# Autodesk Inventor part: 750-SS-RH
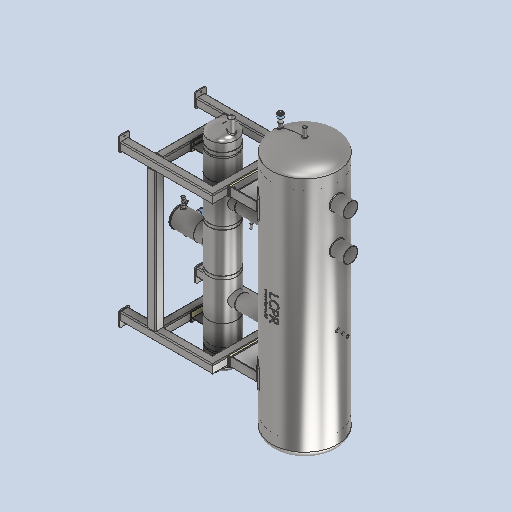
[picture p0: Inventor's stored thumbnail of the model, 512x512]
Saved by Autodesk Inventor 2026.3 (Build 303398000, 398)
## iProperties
Created: 2026-05
Part Number: 750-SS-RH
Material: Generic
Document SubType Name: Modeling
Designer: rva
Density: 1 g/cm^3
Appearance: Default
Author: rva
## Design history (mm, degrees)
derived "LCPR-750-SS-RH.iam"
body "Solid1"
node "LCPR-SS-750-2500-150-WELD.iam:1::750 mm-SS-Dome End Cap.ipt:"
node "LCPR-SS-750-2500-150-WELD.iam:1::750 mm-SS-Dome End Cap.ipt:"
node "LCPR-SS-750-2500-150-WELD.iam:1::H1100-R.ipt:1"
node "LCPR-SS-750-2500-150-WELD.iam:1::LCPR-750-SS-Leg-WELD.iam:1:"
node "LCPR-SS-750-2500-150-WELD.iam:1::LCPR-750-SS-Leg-WELD.iam:2:"
node "LCPR-SS-750-2500-150-WELD.iam:1::LCPR-LOGO.ipt:1"
node "LCPR-SS-750-2500-150-WELD.iam:1::Welds"
node "Sub-SS-300-150-1940-110-75-65-RH.iam:1::300-110-SS-Hole Sub "
node "Sub-SS-300-150-1940-110-75-65-RH.iam:1::300-110-SS-Hole Sub "
node "Sub-SS-300-150-1940-110-75-65-RH.iam:1::300 mm-SS-Subcooler "
node "Sub-SS-300-150-1940-110-75-65-RH.iam:1::300 mm-SS-Subcooler "
node "Sub-SS-300-150-1940-110-75-65-RH.iam:1::1-2 Inch NPT Socket "
node "Sub-SS-300-150-1940-110-75-65-RH.iam:1::Welds"
node "Sub-SS-300-150-1940-110-75-65-RH.iam:1::H1100-R_MIR.ipt:1"
node "LPR-750-Frame Assembly.iam:1::LCPR-SS-750-170 x 120 Frame Fo"
node "LPR-750-Frame Assembly.iam:1::LCPR-SS-750-170 x 120 Frame Fo"
node "LPR-750-Frame Assembly.iam:1::LCPR-SS-750-170 x 120 Frame Fo"
node "LPR-750-Frame Assembly.iam:1::LCPR-SS-750-170 x 120 Frame Fo"
node "Nylon Heat Tranfer Spacer 640x100.ipt:1"
node "Nylon Heat Tranfer Spacer 640x100.ipt:2"
node "AS 1111 - M12 x 140.ipt:1"
node "AS 1112 (4) - Metric M12:1"
node "AS 1237 (4.2) 12 mm:1"
node "AS 1237 (4.2) 12 mm:2"
node "AS 1111 - M12 x 140.ipt:2"
node "AS 1112 (4) - Metric M12:2"
node "AS 1237 (4.2) 12 mm:3"
node "AS 1237 (4.2) 12 mm:4"
node "AS 1111 - M12 x 140.ipt:3"
node "AS 1112 (4) - Metric M12:3"
node "AS 1237 (4.2) 12 mm:5"
node "AS 1237 (4.2) 12 mm:6"
node "AS 1111 - M12 x 140.ipt:4"
node "AS 1112 (4) - Metric M12:4"
node "AS 1237 (4.2) 12 mm:7"
node "AS 1237 (4.2) 12 mm:8"
node "Welds"
node "Nylon Heat Tranfer Spacer 175x100.ipt:1"
node "Nylon Heat Tranfer Spacer 175x100.ipt:2"
node "LCPR-750-SS-RH.iam_Bodies"
